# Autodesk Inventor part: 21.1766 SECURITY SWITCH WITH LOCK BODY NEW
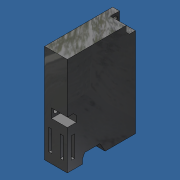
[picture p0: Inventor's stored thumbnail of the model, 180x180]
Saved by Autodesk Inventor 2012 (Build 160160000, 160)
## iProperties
Created: 2016-06
Part Number: 21.1766 SECURITY SWITCH WITH LOCK BODY NEW
Material: ABS Plastic
Document SubType Name: Modeling
Designer: Admin
Density: 1.06 g/cm^3
Mass: 349.292 g
Surface Area: 417.645 cm^2
Volume: 329.521 cm^3
Author: Admin
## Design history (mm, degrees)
feature "Base1"
body "Solid1"
